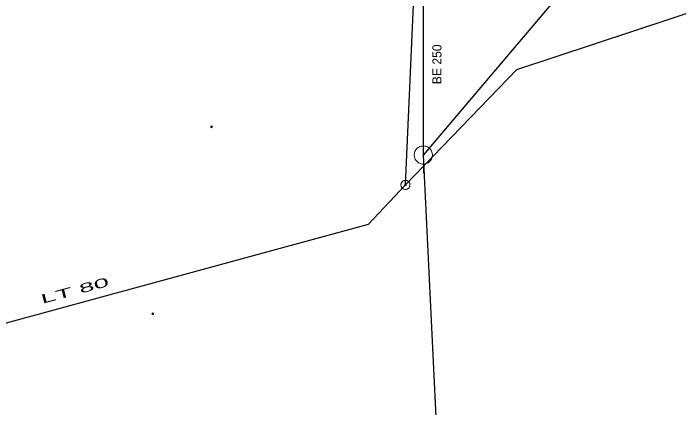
# Model space of a CAD drawing. Extents: x -783064 to -782702, y -1007904 to -1007145.
# Drawn here: x -782982.2 to -782909, y -1007832.9 to -1007789.6 of the extents above; entities that cross this region are included whole.
import ezdxf

# ---------------------------------------------------------------- set-up
doc = ezdxf.new("R2010")
doc.units = 0
doc.header["$LTSCALE"] = 0.4
doc.header["$PDMODE"] = 32
doc.header["$PDSIZE"] = 0.2
for name, color, linetype, lineweight in [('1', 7, 'Continuous', 13), ('14', 7, 'Continuous', 13), ('17', 7, 'Continuous', 25), ('22', 7, 'Continuous', 13), ('47', 7, 'Continuous', 13)]:
    doc.layers.add(name, color=color, linetype=linetype, lineweight=lineweight)

msp = doc.modelspace()

# ---------------------------------------------------------------- linework, layer by layer
at = {"layer": '1'}
for p in [(-782960.356, -1007802.04), (-782966.837, -1007822.595)]:
    msp.add_point(p, dxfattribs=at)
at = {"layer": '14', "lineweight": 25}
for p, q in [((-782937.07, -1007805.14), (-782921.42, -1007786.71)), ((-782933.649, -1007875.42), (-782937.07, -1007805.14))]:
    msp.add_line(p, q, dxfattribs=at)
msp.add_lwpolyline([(-782937.07, -1007805.14), (-782937.05, -1007783.57), (-782937.159, -1007761.59)], dxfattribs=at)
at = {"layer": '17'}
msp.add_line((-782939.04, -1007808.423), (-782936.879, -1007760.179), dxfattribs=at)
for points in [[(-782939.04, -1007808.423), (-782926.774, -1007795.73), (-782824.513, -1007761.893)], [(-782939.04, -1007808.423), (-782943.124, -1007812.766), (-783009.513, -1007830.854)]]:
    msp.add_lwpolyline(points, dxfattribs=at)
at = {"layer": '22'}
msp.add_line((-782937.07, -1007807.14), (-782937.069, -1007804.14), dxfattribs=at)
msp.add_lwpolyline([(-782936.07, -1007805.14), (-782936.075, -1007805.031), (-782936.093, -1007804.923), (-782936.123, -1007804.817), (-782936.163, -1007804.716), (-782936.215, -1007804.619), (-782936.277, -1007804.529), (-782936.349, -1007804.446), (-782936.429, -1007804.372), (-782936.517, -1007804.306), (-782936.611, -1007804.251), (-782936.711, -1007804.206), (-782936.816, -1007804.173), (-782936.923, -1007804.151), (-782937.032, -1007804.141), (-782937.142, -1007804.143), (-782937.25, -1007804.157), (-782937.357, -1007804.182), (-782937.46, -1007804.219), (-782937.558, -1007804.268), (-782937.65, -1007804.326), (-782937.736, -1007804.395), (-782937.813, -1007804.472), (-782937.882, -1007804.558), (-782937.941, -1007804.65), (-782937.989, -1007804.748), (-782938.026, -1007804.851), (-782938.052, -1007804.958), (-782938.066, -1007805.066), (-782938.069, -1007805.176), (-782938.059, -1007805.285), (-782938.038, -1007805.392), (-782938.004, -1007805.496), (-782937.96, -1007805.596), (-782937.905, -1007805.691), (-782937.839, -1007805.779), (-782937.765, -1007805.859), (-782937.682, -1007805.931), (-782937.592, -1007805.993), (-782937.496, -1007806.045), (-782937.394, -1007806.086), (-782937.289, -1007806.116), (-782937.181, -1007806.134), (-782937.071, -1007806.14), (-782936.962, -1007806.134), (-782936.854, -1007806.116), (-782936.749, -1007806.087), (-782936.647, -1007806.046), (-782936.55, -1007805.994), (-782936.46, -1007805.932), (-782936.377, -1007805.861), (-782936.302, -1007805.781), (-782936.237, -1007805.693), (-782936.181, -1007805.599), (-782936.137, -1007805.499), (-782936.103, -1007805.395), (-782936.081, -1007805.287), (-782936.071, -1007805.178)], close=True, dxfattribs=at)
at = {"layer": '47'}
for points in [[(-782938.692, -1007808.063), (-782938.732, -1007808.029), (-782938.774, -1007807.999), (-782938.82, -1007807.974), (-782938.868, -1007807.953), (-782938.918, -1007807.937), (-782938.97, -1007807.928), (-782939.022, -1007807.924), (-782939.074, -1007807.925), (-782939.126, -1007807.93), (-782939.177, -1007807.942), (-782939.227, -1007807.959), (-782939.274, -1007807.982), (-782939.319, -1007808.008), (-782939.361, -1007808.04), (-782939.399, -1007808.075), (-782939.433, -1007808.115), (-782939.463, -1007808.157), (-782939.489, -1007808.204), (-782939.509, -1007808.251), (-782939.525, -1007808.301), (-782939.534, -1007808.353), (-782939.539, -1007808.406), (-782939.538, -1007808.458), (-782939.532, -1007808.509), (-782939.52, -1007808.56), (-782939.503, -1007808.61), (-782939.481, -1007808.658), (-782939.454, -1007808.702), (-782939.422, -1007808.744), (-782939.387, -1007808.782), (-782939.347, -1007808.816), (-782939.305, -1007808.846), (-782939.259, -1007808.873), (-782939.211, -1007808.892), (-782939.161, -1007808.908), (-782939.11, -1007808.918), (-782939.057, -1007808.923), (-782939.005, -1007808.922), (-782938.953, -1007808.915), (-782938.902, -1007808.903), (-782938.852, -1007808.886), (-782938.805, -1007808.865), (-782938.76, -1007808.837), (-782938.718, -1007808.805), (-782938.68, -1007808.77), (-782938.646, -1007808.73), (-782938.616, -1007808.688), (-782938.59, -1007808.643), (-782938.57, -1007808.594), (-782938.554, -1007808.544), (-782938.544, -1007808.493), (-782938.54, -1007808.441), (-782938.541, -1007808.388), (-782938.547, -1007808.336), (-782938.559, -1007808.285), (-782938.576, -1007808.235), (-782938.598, -1007808.189), (-782938.625, -1007808.143), (-782938.657, -1007808.101)], [(-782938.983, -1007808.364), (-782938.989, -1007808.357), (-782938.996, -1007808.353), (-782939.003, -1007808.349), (-782939.011, -1007808.346), (-782939.02, -1007808.343), (-782939.028, -1007808.342), (-782939.037, -1007808.34), (-782939.045, -1007808.341), (-782939.054, -1007808.342), (-782939.062, -1007808.344), (-782939.071, -1007808.347), (-782939.078, -1007808.35), (-782939.085, -1007808.355), (-782939.092, -1007808.359), (-782939.098, -1007808.366), (-782939.105, -1007808.372), (-782939.109, -1007808.379), (-782939.113, -1007808.386), (-782939.116, -1007808.394), (-782939.119, -1007808.403), (-782939.12, -1007808.411), (-782939.122, -1007808.42), (-782939.121, -1007808.428), (-782939.121, -1007808.437), (-782939.118, -1007808.445), (-782939.115, -1007808.454), (-782939.112, -1007808.461), (-782939.107, -1007808.468), (-782939.103, -1007808.475), (-782939.096, -1007808.481), (-782939.09, -1007808.488), (-782939.083, -1007808.492), (-782939.076, -1007808.496), (-782939.068, -1007808.499), (-782939.059, -1007808.502), (-782939.052, -1007808.504), (-782939.042, -1007808.505), (-782939.034, -1007808.504), (-782939.025, -1007808.504), (-782939.017, -1007808.501), (-782939.008, -1007808.498), (-782939.001, -1007808.495), (-782938.994, -1007808.49), (-782938.987, -1007808.486), (-782938.981, -1007808.479), (-782938.974, -1007808.473), (-782938.97, -1007808.466), (-782938.966, -1007808.459), (-782938.963, -1007808.451), (-782938.96, -1007808.442), (-782938.958, -1007808.435), (-782938.957, -1007808.425), (-782938.958, -1007808.417), (-782938.959, -1007808.408), (-782938.961, -1007808.4), (-782938.964, -1007808.391), (-782938.967, -1007808.384), (-782938.972, -1007808.377), (-782938.976, -1007808.37)]]:
    msp.add_lwpolyline(points, close=True, dxfattribs=at)

# ---------------------------------------------------------------- texts
at = {"layer": '1'}
msp.add_text('BE 250', height=1, rotation=90, dxfattribs=at).set_placement((-782935.076, -1007797.356))
at = {"layer": '1', "width": 2.25}
msp.add_text('LT 80 ', height=1, rotation=15, dxfattribs=at).set_placement((-782978.989, -1007821.516))

doc.saveas('drawing.dxf')
